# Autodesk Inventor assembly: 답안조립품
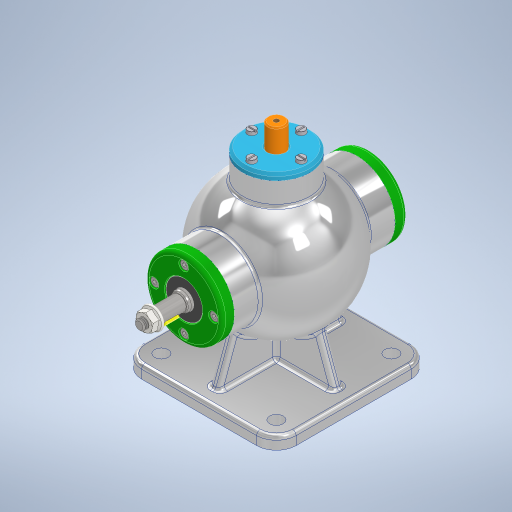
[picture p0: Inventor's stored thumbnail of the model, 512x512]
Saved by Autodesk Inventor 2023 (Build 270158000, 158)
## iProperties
Created: 2023-07
Part Number: 답안조립품
Document SubType Name: Assembly
Designer: Owner
Author: Owner
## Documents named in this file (16)
- C:\Users\Owner\Desktop\730711V1001\답안조립품.iam
- C:\Users\Owner\Desktop\730711V1001\본체.ipt
- C:\Users\Owner\Desktop\730711V1001\V-벨트풀리.ipt
- C:\Users\Owner\Desktop\730711V1001\너트 M8.ipt
- C:\Users\Owner\Desktop\730711V1001\뒤커버.ipt
- C:\Users\Owner\Desktop\730711V1001\베어링- 6202.ipt
- KS B 2023 - 6202 - 15 x 35 x 11 - 7.8.ipt
- C:\Users\Owner\Desktop\730711V1001\볼트 M4 x 12.ipt
- C:\Users\Owner\Desktop\730711V1001\볼트 M4 x 16.ipt
- C:\Users\Owner\Desktop\730711V1001\상부커버.ipt
- C:\Users\Owner\Desktop\730711V1001\슬라이드.ipt
- C:\Users\Owner\Desktop\730711V1001\앞커버.ipt
- C:\Users\Owner\Desktop\730711V1001\오일실 15 30 7.ipt
- C:\Users\Owner\Desktop\730711V1001\칼라.ipt
- C:\Users\Owner\Desktop\730711V1001\키 4 x 4 x 12.ipt
- C:\Users\Owner\Desktop\730711V1001\편심축.ipt
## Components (15 placed, 4 different names)
1. V-벨트풀리:1
2. KS B 2023 - 6202 - 15 x 35 x 11 - 7.8:1
3. KS B 2023 - 6202 - 15 x 35 x 11 - 7.8:2
4. ISO 4762 M4 x 16:6
5. ISO 4762 M4 x 16:10
6. ISO 4762 M4 x 16:11
7. ISO 4762 M4 x 16:12
8. ISO 4762 M4 x 16:13
9. ISO 4762 M4 x 16:14
10. ISO 4762 M4 x 16:15
11. ISO 4762 M4 x 16:16
12. KS B 1021 - 에 따름 ISO 1207 - 미터 A  M 4 x 12:1
13. KS B 1021 - 에 따름 ISO 1207 - 미터 A  M 4 x 12:2
14. KS B 1021 - 에 따름 ISO 1207 - 미터 A  M 4 x 12:3
15. KS B 1021 - 에 따름 ISO 1207 - 미터 A  M 4 x 12:4
